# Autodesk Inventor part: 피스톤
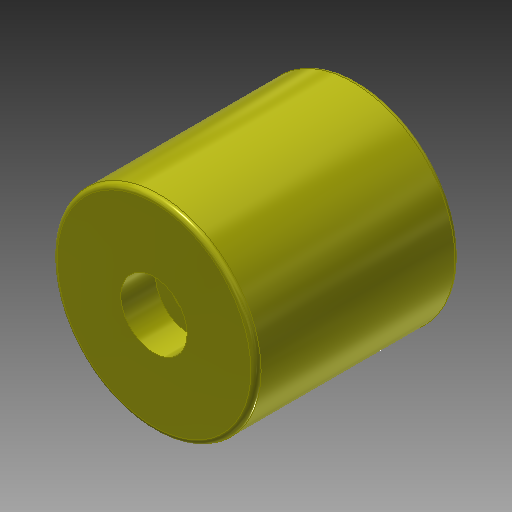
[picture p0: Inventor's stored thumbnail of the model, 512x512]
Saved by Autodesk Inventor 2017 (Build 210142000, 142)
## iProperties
Created: 2018-01
Part Number: 피스톤
Material: 강철, 탄소
Document SubType Name: Modeling
Designer: mduedu
Density: 7.87 g/cm^3
Mass: 44.9853 g
Surface Area: 21.9333 cm^2
Volume: 5.71605 cm^3
Appearance: 노란색
Author: mduedu
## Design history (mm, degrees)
sketch "스케치1"
  geometry: C1 r 10 at (0, 0); 1 further point
  constraints: 1 centre point, 1 coincident
  dimensions: "d0" = 20 diameter of C1
extrude "돌출1" new body sketch "스케치1" distance "d1" = 20; taper "d2" = 0 deg
hole "구멍1" diameter "d5" = 7; stored, may be unused: countersink angle "d9" = 90 deg, drill point angle "d11" = 0 deg; dims "d6" = 6, "d7" = 4, "d8" = 2, "d10" = 10, "d12" = 10, "d13" = 10
chamfer "모따기1" distance "d14" = 0.5; stored, may be unused: second distance "d15" = 2, angle "d16" = 45 deg
fillet "모깎기1" dims "d17" = 0.5
sketch "스케치2"
  geometry: 2 further points
  constraints: 1 coincident
sketch "스케치3"
  geometry: 2 further points
  constraints: 1 coincident
hole "구멍2" sketch "스케치3" at (0, 0) diameter "d18" = 3.4; stored, may be unused: countersink angle "d22" = 90 deg, drill point angle "d24" = 0 deg; dims "d19" = 6, "d20" = 6.5, "d21" = 3.4, "d23" = 8
node "솔리드1"
